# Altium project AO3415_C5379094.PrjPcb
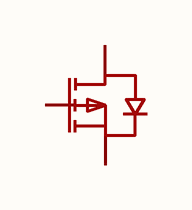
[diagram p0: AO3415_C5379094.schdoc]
1 sheet, 1 parts. Net scope: global (net labels, ports and power ports of the same name join across sheets).

## Sheet AO3415_C5379094.schdoc
size 127 x 101 mm

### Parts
Q?  ao3415_c5379094  [SOT-23-3_L2.9-W1.6-P1.90-LS2.8-BR]  (value not drawn)

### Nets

Not connected (* = marked no-connect by the designer): Q? 1(G) 2(S) 3(D)

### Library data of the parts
Q? = ao3415_c5379094: 数量:1个P沟道;漏源电压(Vdss):20V;连续漏极电流(Id):4.5A;导通电阻(RDS(on)):40mΩ@4.5V;耗散功率(Pd):1.5W;阈值电压(Vgs(th)):650mV;; Manufacturer: MSKSEMI(美森科); ManufacturerPart: AO3415; AddInBom: yes; ModelId: 89cb27a44ab2466697082bb9fd73a7d0; ModelName: SOT-23-3L_L2.9-W1.6-H1.1-LS2.8-P0.95; ModelTransform: 114.173,110.236,0,90,0,0,0,0,0; Number: 1个P沟道; Drain to Source Voltage: 20V; Current - Continuous Drain(Id): 4.5A; Pd - Power Dissipation: 1.5W; Gate Threshold Voltage (Vgs(th)): 650mV; Gate Charge(Qg): 9.6nC@4.5V; Input Capacitance(Ciss): 850pF; Reverse Transfer Capacitance (Crss@Vds): 55pF; Output Capacitance(Coss): 70pF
